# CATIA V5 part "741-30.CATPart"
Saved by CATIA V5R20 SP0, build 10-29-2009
Part number: 741-30
Bounding box of the stored display mesh (mm): x -28 to 28, y -28 to 28, z -30 to 45
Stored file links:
  C:\Users\Utente\Desktop\IO LAVORO\3D X SITO CF\X SITO\741\741-30.CATPart
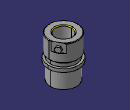
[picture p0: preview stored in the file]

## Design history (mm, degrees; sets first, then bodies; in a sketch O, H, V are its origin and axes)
Set1
  DatumSurface1 to DatumSurface42 "741-30"
Body1 (main body)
